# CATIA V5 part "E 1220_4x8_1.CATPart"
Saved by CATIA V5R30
Part number: Sroub_M4x8
Definition: E 1220_4x8_1
Nomenclature: E 1220_4x8_1
Source: Unknown
Description: PART--DESC
Bounding box of the stored display mesh (mm): x -6.429 to 2.991, y -9.663 to -1.444, z -16 to -8
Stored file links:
  E:\Bakalarka\Model\Forma_v7\E 1220_4x8_1.CATPart
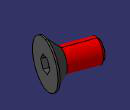
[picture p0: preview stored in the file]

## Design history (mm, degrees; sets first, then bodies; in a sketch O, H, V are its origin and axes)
Body1 "MANIFOLD_SOLID_BREP #205" (main body)
  Solid1: solid without history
